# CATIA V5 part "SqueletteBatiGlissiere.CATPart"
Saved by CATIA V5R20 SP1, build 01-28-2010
Part number: SqueletteBatiGlissiere
Publications: "Plan.1", "Point.2", "Droite.2", "Point.3", "Point.4", "Point.5", "Point.6", "Droite.3", "Droite.4", "Droite.5", "Droite.6", "Point.7", "Point.8", "Point.9", "Point.10", "Droite.7", "Droite.8", "Droite.9", "Droite.10"
Bounding box of the stored display mesh (mm): x 0 to 50, y -230 to 230, z -15 to 15
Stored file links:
  C:\Documents and Settings\ndumont\Bureau\ndumont_CAO\SqueletteBatiGlissiere.CATPart
  C:\Documents and Settings\ndumont\Bureau\ndumont_CAO\Squelette.CATProduct
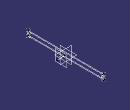
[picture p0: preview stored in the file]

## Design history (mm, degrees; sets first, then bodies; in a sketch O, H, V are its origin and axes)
Parameters
  CourseCoulisseau = 400 mm {= 4*External.LongueurAB}
  EpaisseurGlissiere = 5 mm
External parameters (linked from other documents)
  External.LargeurCoulisseau = 20 mm
  External.LongueurAB = 100 mm
  External.EpaisseurABetDC = 20 mm
  External.EpaisseurCoulisseau = 20 mm
  External.DiametreTrousABetDC = 18 mm
  External.DiametrePivotABetDC = 40 mm
  External.LongueurDC = 200 mm
  External.LongueurCoulisseau = 40 mm
Set1
  Plane1: type Offset, RefPlane yz-plane, Offset 30 {= (3*External.EpaisseurABetDC )/2}
  Point1: type OnPlane, Support Plane1, H 0, V 0, Direction (0, 1, 0)
  Line1: type PtDir, RefPoint Point1, Direction Plane1, Start -20, End 20
  Point2: (0, -225 {= -((CourseCoulisseau /2)+(External.LongueurCoulisseau /2)+5mm)}, 10 {= External.LargeurCoulisseau /2})
  Point3: (0, -225 {= -((CourseCoulisseau /2)+(External.LongueurCoulisseau /2)+5mm)}, -10 {= -External.LargeurCoulisseau /2})
  Point4: (0, 225 {= (CourseCoulisseau /2)+(External.LongueurCoulisseau /2)+5mm}, 10 {= External.LargeurCoulisseau /2})
  Point5: (0, 225 {= (CourseCoulisseau /2)+(External.LongueurCoulisseau /2)+5mm}, -10 {= -External.LargeurCoulisseau /2})
  Line2: type PtPt, FirstPoint Point4, SecondPoint Point2
  Line3: type PtPt, FirstPoint Point2, SecondPoint Point3
  Line4: type PtPt, FirstPoint Point3, SecondPoint Point5
  Line5: type PtPt, FirstPoint Point5, SecondPoint Point4
  Point6: (0, -230 {= -((CourseCoulisseau /2)+(External.LongueurCoulisseau /2)+EpaisseurGlissiere +5mm)}, 15 {= (External.LargeurCoulisseau /2)+EpaisseurGlissiere})
  Point7: (0, -230 {= -((CourseCoulisseau /2)+(External.LongueurCoulisseau /2)+EpaisseurGlissiere +5mm)}, -15 {= -((External.LargeurCoulisseau /2)+EpaisseurGlissiere )})
  Point8: (0, 230 {= (CourseCoulisseau /2)+(External.LongueurCoulisseau /2)+EpaisseurGlissiere +5mm}, 15 {= (External.LargeurCoulisseau /2)+EpaisseurGlissiere})
  Point9: (0, 230 {= (CourseCoulisseau /2)+(External.LongueurCoulisseau /2)+EpaisseurGlissiere +5mm}, -15 {= -((External.LargeurCoulisseau /2)+EpaisseurGlissiere )})
  Line6: type PtPt, FirstPoint Point8, SecondPoint Point6
  Line7: type PtPt, FirstPoint Point6, SecondPoint Point7
  Line8: type PtPt, FirstPoint Point7, SecondPoint Point9
  Line9: type PtPt, FirstPoint Point9, SecondPoint Point8
Body1 (main body)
